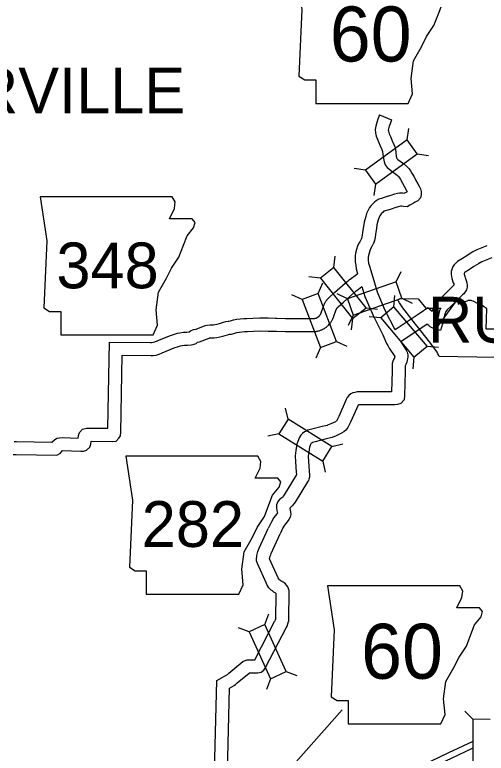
# Model space of a CAD drawing. Extents: x 535214 to 694517, y 381272 to 484355.
# Drawn here: x 547357 to 552787, y 463649 to 472159 of the extents above; entities that cross this region are included whole.
import ezdxf

# ---------------------------------------------------------------- set-up
doc = ezdxf.new("R2010")
doc.units = 0
for name, color, linetype in [('Level 10', 7, 'Continuous'), ('Level 11', 7, 'Continuous'), ('Level 19', 7, 'Continuous'), ('Level 20', 7, 'Continuous'), ('Level 21', 7, 'Continuous'), ('Level 6', 7, 'Continuous')]:
    doc.layers.add(name, color=color, linetype=linetype)

msp = doc.modelspace()

# ---------------------------------------------------------------- linework, layer by layer
at = {"layer": 'Level 10'}
msp.add_line((551558.8, 471004), (551697.7, 470947.3), dxfattribs=at)
for points in [[(551329.5, 469541.8), (551321.4, 469527.2), (551305.6, 469491), (551293.3, 469454.9), (551283, 469413.3), (551278.1, 469380.9), (551276.4, 469344.8), (551278.6, 469311.5), (551284.2, 469274.4), (551289.4, 469232.4), (551303.8, 469174.6)], [(551485.5, 469518), (551471.2, 469488.3), (551456.1, 469460.8), (551445.5, 469436.6), (551437.3, 469412.6), (551430.2, 469384), (551427.5, 469366.3), (551426.6, 469346.3), (551427.9, 469327.6), (551432.8, 469294.9), (551441.8, 469260.9), (551468.3, 469172.2)], [(550359, 468663.4), (550373.9, 468663), (550475.7, 468660.2), (550571.1, 468659.6), (550657.3, 468659), (550792.5, 468658.2), (550797.1, 468658.2), (550801, 468658.4), (550805.1, 468658.8), (550807.2, 468659.1), (550811.5, 468659.8), (550813.8, 468660.2), (550816.3, 468660.8), (550818.8, 468661.4), (550821.3, 468662.1), (550823.6, 468662.8), (550827.5, 468664.1), (550831.3, 468665.6), (550833.5, 468666.5), (550835.8, 468667.6), (550838.2, 468668.7), (550840.5, 468669.9), (550842.7, 468671.1), (550845, 468672.5), (550847.2, 468673.8), (550849.3, 468675.3), (550851.2, 468676.6), (550854.7, 468679.2), (550856.6, 468680.7), (550858.5, 468682.4), (550860.7, 468684.2), (550861.4, 468685), (550862.4, 468685.8), (550863.3, 468686.8), (550863.7, 468687.1), (550868, 468691.8), (550869.4, 468693.4), (550871.1, 468695.4), (550872.6, 468697.5), (550874, 468699.4), (550876.5, 468703), (550877.6, 468704.7), (550879.8, 468708.5), (550881, 468710.6), (550882, 468712.6), (550884, 468716.8), (550884.2, 468717.3), (550885.3, 468719.9), (550886.3, 468722.4), (550887.3, 468725.3), (550913.2, 468800.7), (550916.5, 468809.9), (550920.1, 468818.6), (550924.1, 468827.3), (550929.3, 468837.5), (550933.4, 468844.7), (550937.5, 468851.5), (550941.1, 468857), (550943.5, 468860.6), (550947.4, 468866), (550952.7, 468873.1), (550956.1, 468877.3), (550958, 468879.5), (550959.9, 468881.7), (550964.2, 468886.7), (550970.6, 468893.4), (550978.1, 468900.7), (551041.4, 468957.6), (551163.9, 469067.5), (551170.1, 469073), (551179.9, 469081.3), (551186.6, 469086.8), (551195.4, 469093.7), (551203.4, 469099.8), (551207.3, 469102.7), (551303.8, 469174.6)], [(551468.3, 469172.2), (551532, 468964.8), (551558.8, 468901.8), (551619.8, 468755.1), (551731.1, 468540.5), (551737.8, 468527.7)], [(550354.8, 468513.5), (550369.8, 468513), (550473.2, 468510.2), (550570.1, 468509.6), (550656.4, 468509), (550793, 468508.2), (550802.1, 468508.3), (550811.8, 468508.8), (550821.3, 468509.7), (550828.3, 468510.6), (550837.5, 468512), (550844.1, 468513.3), (550850.5, 468514.7), (550856.8, 468516.3), (550863.1, 468518), (550869.6, 468520), (550878.6, 468523.1), (550887.5, 468526.5), (550893.8, 468529.1), (550899.7, 468531.8), (550905.6, 468534.7), (550911.4, 468537.7), (550917.1, 468540.9), (550922.7, 468544.2), (550928.3, 468547.6), (550933.7, 468551.2), (550939.2, 468555.1), (550946.7, 468560.7), (550952, 468564.9), (550956.9, 468569.1), (550961.6, 468573.3), (550964.2, 468575.7), (550966.6, 468577.9), (550968.9, 468580.2), (550971.7, 468583.1), (550979.8, 468591.7), (550984.4, 468597), (550988.5, 468602.1), (550992.5, 468607.2), (550996.5, 468612.7), (551001.7, 468620.4), (551005.5, 468626.3), (551010.2, 468634.3), (551013.5, 468640.2), (551016.6, 468646.3), (551020.4, 468654.4), (551022.1, 468658.1), (551024.5, 468663.9), (551026.8, 468670), (551028.9, 468675.7), (551054.6, 468750.5), (551056.3, 468755.4), (551057.7, 468758.7), (551059.1, 468761.9), (551061.5, 468766.5), (551062.9, 468769), (551064.6, 468771.8), (551066.1, 468774.1), (551066.8, 468775.1), (551068.3, 468777.3), (551070.9, 468780.6), (551072.1, 468782.2), (551072.7, 468782.8), (551073.2, 468783.4), (551075, 468785.5), (551077.6, 468788.2), (551080.7, 468791.3), (551141.6, 468846), (551263.7, 468955.5), (551268.3, 468959.6), (551275.9, 468966.1), (551280.4, 468969.8), (551287, 468975), (551293, 468979.5), (551296.6, 468982.1), (551356.1, 469026.5)], [(551356.1, 469026.5), (551390.9, 468913.3), (551420.5, 468843.6), (551483.7, 468691.7), (551598, 468471.4), (551639.5, 468372.5)], [(552026.8, 468721.3), (551737.8, 468527.7)], [(552106, 468593.8), (551801.9, 468390.1)]]:
    msp.add_lwpolyline(points, dxfattribs=at)
at = {"layer": 'Level 11'}
for points in [[(551558.8, 471004), (551539, 470955.5), (551525.9, 470917.9), (551515.9, 470876.1), (551508.6, 470838.6), (551510.6, 470798.5), (551519.2, 470760.3), (551529.4, 470731.7), (551546.7, 470693.5), (551567, 470646.7), (551585.3, 470606.1), (551590, 470593.3), (551593.1, 470581.8), (551595.4, 470553.7), (551603, 470502.5), (551611, 470465.2), (551624.5, 470431), (551647.8, 470399.1), (551675, 470374.4), (551709.4, 470349.4), (551743.2, 470325.7), (551770.4, 470301.8), (551781.5, 470290.2), (551788.2, 470280.1), (551801.3, 470258.7), (551823.7, 470218.1), (551843, 470182.5), (551869.3, 470135.4), (551878.1, 470120.2), (551870.6, 470115.3), (551855.2, 470106.7), (551839.5, 470099.8), (551826.1, 470103.9), (551789, 470103.6), (551765.6, 470098.1), (551730.3, 470090), (551688.5, 470075.9), (551645.8, 470063), (551612, 470051.6), (551581.3, 470043.4), (551563, 470037.3), (551540.7, 470029.3), (551518.7, 470013.4), (551502.2, 470000.1), (551481, 469981.7), (551461.2, 469960.1), (551444.2, 469937.2), (551431.2, 469915.4), (551419.8, 469893.2), (551408, 469868.2), (551399, 469834), (551381.6, 469768.3), (551373.8, 469720.8), (551363.2, 469651.8), (551358.7, 469616.1), (551354.9, 469597.9), (551349.1, 469580.5), (551337.8, 469556.9), (551329.5, 469541.8)], [(551697.7, 470947.3), (551679.3, 470902.4), (551670, 470875.8), (551662.6, 470844.4), (551659.3, 470827.8), (551659.8, 470818.9), (551663.5, 470802.2), (551668.6, 470787.9), (551683.9, 470754.3), (551704.2, 470707.4), (551724.5, 470662.4), (551733.2, 470638.3), (551741.4, 470607.9), (551744.5, 470571), (551750.7, 470529.2), (551755.1, 470508.6), (551756.9, 470503.9), (551759.8, 470500), (551769.8, 470491), (551796.6, 470471.5), (551836.1, 470443.8), (551874.2, 470410.3), (551899.3, 470384.2), (551914.8, 470360.5), (551931, 470334.1), (551955.3, 470290.1), (551974.4, 470254.9), (551999.8, 470209.4), (552020, 470174.4), (552031.2, 470151.5), (552038.9, 470120.5), (552037.2, 470085.7), (552029.6, 470051.1), (552000, 470014.7), (551968.5, 470000.2), (551948.6, 469987), (551922.2, 469972.3), (551906.2, 469965.2), (551876.8, 469947.2), (551834.9, 469948.2), (551811, 469951.5), (551805.2, 469953.3), (551799.5, 469952), (551771.2, 469945.5), (551734.3, 469933), (551691.4, 469920.1), (551655.5, 469908), (551624.5, 469899.6), (551612, 469895.5), (551611.4, 469895.3), (551609.6, 469894), (551598.3, 469885), (551585.8, 469874.1), (551577, 469864.4), (551569.3, 469854), (551562.5, 469842.7), (551554.3, 469826.7), (551549.5, 469816.5), (551544, 469795.7), (551528.4, 469737), (551521.9, 469697.3), (551511.7, 469631.1), (551506.8, 469591.6), (551500, 469558.7), (551488.3, 469524), (551485.5, 469518)], [(552792.3, 469494.6), (552677.1, 469448.4), (552649.9, 469435.4), (552634.1, 469426.9), (552615, 469413.6), (552564.1, 469382.5), (552514.5, 469349.4), (552457.2, 469315.8), (552435.3, 469297.3), (552416.9, 469278.6), (552402.2, 469257.3), (552393.1, 469233.4), (552384.7, 469201.1), (552383.3, 469165.7), (552386.7, 469143.5), (552391.1, 469121.4), (552407.9, 469070.9), (552412.7, 469056.7), (552414.8, 469046.1), (552415.2, 469043.4), (552414.3, 469042.2), (552407.9, 469035.4), (552275.2, 468905.6), (552233.3, 468865.5), (552208.9, 468841.2), (552186.5, 468815.8)], [(552852, 469356.9), (552737.4, 469311), (552717.8, 469301.6), (552712.8, 469298.9), (552697.2, 469287.9), (552644.8, 469256.1), (552594.2, 469222.3), (552544.2, 469192.9), (552537.4, 469187.2), (552535.6, 469185.4), (552533.9, 469178.9), (552533.7, 469174.2), (552534.5, 469169.5), (552536.4, 469159.7), (552550.2, 469118.4), (552557.7, 469095.7), (552562.8, 469071.3), (552565.9, 469048), (552566.1, 469020.4), (552559, 468987.7), (552543.9, 468964.5), (552528.5, 468944.8), (552515.2, 468930.5), (552379.5, 468797.9), (552338.2, 468758.2), (552320.2, 468740.3)], [(552186.3, 468815.9), (552163.7, 468740.8), (552113.9, 468783.5), (552024.9, 468720)], [(552320.2, 468740.3), (552307.8, 468699), (552293.5, 468634.4), (552261.7, 468521.8), (552170.3, 468545.9), (552142.4, 468561.4), (552125.6, 468577.3), (552110.1, 468590.3), (552106.1, 468593.7)], [(547350.5, 467240.4), (547375.8, 467240.6), (547784.9, 467234.1), (547813.8, 467261.7), (547843.6, 467278.2), (547873.9, 467285), (547902.6, 467286.8), (548089.2, 467279.7), (548091.8, 467312.1), (548104.3, 467345), (548135.7, 467383.4), (548184.7, 467394.6), (548208.8, 467394.8), (548429.8, 467393.4), (548448.6, 468386.7), (548921, 468381.9), (548937.5, 468382.4), (548951.8, 468384.5), (548970.1, 468390.2), (548999.2, 468401.8), (549141.1, 468460.7), (549196.4, 468479.5), (549229.8, 468489.1), (549260.2, 468495.3), (549299.8, 468501), (549340.7, 468502.5), (549367.5, 468503.4), (549380.3, 468514.9), (549414.9, 468530.3), (549445.6, 468535.3), (549550.7, 468577.5), (549574.5, 468582.6), (549607.1, 468586.7), (549643.7, 468587.6), (549662.7, 468590.1), (549688.4, 468594.1), (549715, 468601.1), (549762.3, 468615.1), (549788.4, 468623.2), (549815.5, 468626.3), (549824.4, 468627), (549843.1, 468631.6), (549878.1, 468641.5), (549913.3, 468649.4), (549954.3, 468655.4), (549994.4, 468658.6), (550031.8, 468659.4), (550100.7, 468663), (550181.5, 468664.8), (550276, 468664.6), (550373.9, 468663)], [(547340.6, 467090.3), (547375.2, 467090.6), (547840.1, 467083.2), (547884.4, 467105.9), (547901.5, 467132), (547904.4, 467136.6), (548117.9, 467128.5), (548147.8, 467129.5), (548185.3, 467139.7), (548221.1, 467176.3), (548232, 467211.3), (548236.6, 467240.6), (548236.9, 467244.7), (548480.3, 467243.1), (548524.4, 467246.9), (548554.8, 467277.9), (548575.8, 467307.1), (548578.9, 467347.8), (548595.8, 468235.2), (548922.6, 468231.8), (548951.1, 468232.7), (548985.6, 468238), (549020, 468248.7), (549055.6, 468262.8), (549194.1, 468320.3), (549241.2, 468336.3), (549265.6, 468343.3), (549286, 468347.5), (549313.2, 468351.4), (549346.1, 468352.6), (549387.7, 468354.1), (549412.7, 468359.1), (549444.9, 468371.4), (549461, 468385.8), (549486.1, 468389.9), (549594.8, 468433.5), (549599.9, 468434.6), (549618.2, 468437), (549655.4, 468437.8), (549684.3, 468441.6), (549719.3, 468447.1), (549755.4, 468456.7), (549805.7, 468471.5), (549819.4, 468475.8), (549830.2, 468477), (549848.2, 468478.5), (549881.3, 468486.4), (549915, 468496.1), (549940.6, 468501.8), (549971.3, 468506.3), (550002, 468508.7), (550037.4, 468509.5), (550106.2, 468513.1), (550183, 468514.8), (550276, 468514.6), (550369.8, 468513)], [(551639.5, 468372.5), (551653.4, 468347.4), (551669.4, 468318.7), (551733.8, 468219.6), (551732.5, 468214.4), (551729.4, 468201.7), (551727.4, 468196.8), (551716, 468179), (551702.2, 468140)], [(551801.9, 468390.1), (551865.3, 468292.5), (551878, 468269.3), (551885.4, 468241.8), (551885.7, 468216), (551881.7, 468192.6), (551878.2, 468178.6), (551872.5, 468155.2), (551860.9, 468127), (551852.4, 468113.8)], [(551702.2, 468140), (551702.9, 468050.3)], [(551852.4, 468113.8), (551852.9, 468051.5)], [(551702.9, 468052.7), (551697.3, 467814.9), (551670.5, 467814.6), (551328.9, 467814.7), (551300.8, 467813.1), (551273.5, 467807.1), (551251.8, 467800.7), (551228.9, 467790.1), (551204.8, 467771.1), (551184.8, 467747.1), (551175, 467725.2), (551089.6, 467527.8), (551066, 467482.1), (551061.2, 467475.5), (551060.1, 467474.6), (551049.6, 467468.5), (550997.9, 467444.1), (550960.8, 467428.9), (550954.4, 467426.9), (550897.7, 467413.3), (550778, 467382.9), (550733.8, 467370.1), (550716.3, 467361.8), (550695.1, 467351.7), (550671.9, 467334.9), (550651.1, 467312.7), (550632.3, 467282.6), (550624.1, 467262.1), (550617, 467243.1), (550607.4, 467209.9), (550593.7, 467138.7), (550587.3, 467076.4), (550589.5, 467007.5), (550597.7, 466886.2), (550601.4, 466855.4), (550601.4, 466855.4), (550599.4, 466851.6), (550461.4, 466627.7), (550451, 466613.4), (550441.7, 466601.4), (550431.2, 466591.3), (550411.9, 466576.5), (550386.7, 466550.8), (550372.1, 466511.2), (550373.4, 466476.8), (550376.8, 466444.5), (550382.9, 466417.1), (550375.8, 466408), (550359.6, 466388.3), (550338.9, 466359.9), (550328.2, 466341.7), (550313.7, 466317.3), (550276.9, 466239.8)], [(551852.9, 468049.1), (551846.3, 467770.1), (551842.9, 467719.5), (551802.6, 467680.9), (551765, 467666.4), (551735.5, 467665.2), (551671.1, 467664.6), (551333.3, 467664.7), (551321.4, 467664), (551311, 467661.7), (551225.3, 467463.5), (551193.8, 467402.7), (551172, 467373), (551147.3, 467351.7), (551119.1, 467335.5), (551058.5, 467306.8), (551011.1, 467287.4), (550993.6, 467282.1), (550933.7, 467267.7), (550817.4, 467238.1), (550787, 467229.3), (550780.6, 467226.3), (550772, 467222.2), (550771.4, 467221.8), (550770.5, 467220.7), (550766.6, 467214.6), (550764, 467208), (550759.5, 467195.9), (550753.5, 467175), (550742.3, 467116.9), (550737.6, 467071.1), (550739.4, 467014.9), (550747.1, 466900.3), (550752.4, 466856.8), (550751.3, 466829.8), (550744.2, 466809), (550738.4, 466793), (550728.7, 466775.7), (550586, 466544), (550570.8, 466523.1), (550553.4, 466500.8), (550529.3, 466477.6), (550524.5, 466473.9), (550525, 466468.9), (550533.2, 466432.5), (550537.3, 466399.4), (550527.9, 466370.5), (550515, 466342.2), (550492.6, 466313.9), (550478.2, 466296.4), (550464.4, 466277.5), (550457.4, 466265.5), (550446.3, 466246.7), (550412.4, 466175.5)], [(550364.1, 465494), (550358, 465498), (550342.4, 465506.5), (550324.1, 465519.2), (550310.9, 465528.4), (550297.2, 465540.1), (550282.7, 465555.7), (550272.1, 465573.8), (550264.9, 465587.3), (550256.2, 465603.5), (550153.1, 465834.7), (550142.3, 465864.9), (550142.1, 465893.4), (550143.5, 465912.5), (550146, 465925.9), (550147.4, 465941.7), (550157.6, 465972.4), (550165.6, 465992.9), (550173.3, 466010.8), (550276.3, 466238.6)], [(550515.4, 465532.2), (550502.2, 465565.5), (550488.5, 465585.8), (550473.7, 465600.4), (550458.7, 465612.3), (550447.1, 465619.1), (550434.7, 465627), (550421.2, 465634.4), (550409.5, 465642.5), (550403.1, 465647), (550397.2, 465658), (550390.8, 465669.8), (550292.4, 465890.8), (550292.3, 465891), (550292.5, 465893.1), (550294.8, 465905.7), (550295.3, 465911), (550298.7, 465921.4), (550304.5, 465936.1), (550310.6, 465950.3), (550413, 466176.7)], [(550515.4, 465532.2), (550509.8, 465166.2)], [(550364.8, 465494), (550360.1, 465190.5)], [(549658.9, 463437.2), (549683.6, 464485.7), (549799.6, 464553.1), (549805.7, 464558), (549823.7, 464573.3), (549960.8, 464685.6), (549985.8, 464706.5), (550009.3, 464716.6), (550034.4, 464724.1), (550059.7, 464725.2), (550120.7, 464726.2), (550350, 465165.4), (550354.4, 465173.4), (550359.9, 465190.5)], [(549809, 463437.7), (549831.6, 464398.2), (549884.5, 464429), (549901.1, 464442.2), (549919.9, 464458.2), (550056.5, 464570), (550062.6, 464575.2), (550064, 464575.2), (550156, 464576.9), (550193.5, 464581.6), (550226.2, 464607.8), (550241, 464630.3), (550247.9, 464645.8), (550482.4, 465094.8), (550492.8, 465113.9), (550509.8, 465166.2)]]:
    msp.add_lwpolyline(points, dxfattribs=at)
at = {"layer": 'Level 19'}
for points in [[(550841.5, 462935.6), (551248.7, 463128.5), (551677.6, 463332.6), (552045.5, 463507.2), (552357.6, 463655.9), (552628.9, 463785.1)], [(550844.5, 462861), (551278.2, 463066.4), (551707.1, 463270.5), (552075, 463445.1), (552387.2, 463593.8), (552628.9, 463708.9)]]:
    msp.add_lwpolyline(points, dxfattribs=at)
at = {"layer": 'Level 20'}
for p, q in [((551875.5, 470717.7), (551895.6, 470848.1)), ((551992.6, 470558), (552123, 470537.9)), ((551396.4, 470366.5), (551266, 470386.6)), ((551513.5, 470206.8), (551493.4, 470076.4)), ((551031.7, 469246.4), (551046.3, 469377.6)), ((551751, 469080.4), (551808.4, 469199.3)), ((550877.1, 469122.7), (550745.9, 469137.3)), ((550852.2, 468948.4), (550906.4, 469068.8)), ((550667, 468878.3), (550546.6, 468932.6)), ((551190.1, 468885), (551071.2, 468942.4)), ((551723.8, 468794), (551735.5, 468925.5)), ((551816.2, 468893.5), (551935, 468836)), ((551402.7, 468782.5), (551533.9, 468767.8)), ((551255.2, 468698), (551197.8, 468579.1)), ((551248, 468658.8), (551233.4, 468527.6)), ((551572, 468666.9), (551440.5, 468678.6)), ((550877.3, 468322.8), (550823, 468202.5)), ((551062.5, 468392.9), (551182.8, 468338.6)), ((552105.1, 468338.5), (552236.5, 468326.8)), ((551953.2, 468211.4), (551941.6, 468079.9)), ((550505.4, 467498.3), (550475.7, 467627)), ((550400.3, 467330.5), (550271.7, 467300.9)), ((551008.9, 467183.3), (551137.5, 467212.9)), ((550903.9, 467015.4), (550933.5, 466886.8)), ((550237.3, 465130.6), (550283.9, 465254.1)), ((550056.9, 465048.9), (549933.4, 465095.5)), ((550482.3, 464589.5), (550605.8, 464542.9)), ((550301.9, 464507.8), (550255.4, 464384.3)), ((552634.3, 464040.1), (552541.4, 464134)), ((552634.3, 464040.1), (552631, 463462.2)), ((552832.3, 464039), (552634.3, 464040.1))]:
    msp.add_line(p, q, dxfattribs=at)
for points in [[(551513.5, 470206.8), (551992.6, 470558), (551875.5, 470717.7), (551396.4, 470366.5)], [(550877.1, 469122.7), (551248, 468658.8), (551402.7, 468782.5), (551031.7, 469246.4)], [(551751, 469080.4), (551190.1, 468885), (551255.2, 468698), (551816.2, 468893.5)], [(550667, 468878.3), (550877.3, 468322.8), (551062.5, 468392.9), (550852.2, 468948.4)], [(551572, 468666.9), (551953.2, 468211.4), (552105.1, 468338.5), (551723.8, 468794)], [(551008.9, 467183.3), (550505.4, 467498.3), (550400.3, 467330.5), (550903.9, 467015.4)], [(550482.3, 464589.5), (550237.3, 465130.6), (550056.9, 465048.9), (550301.9, 464507.8)]]:
    msp.add_lwpolyline(points, close=True, dxfattribs=at)
at = {"layer": 'Level 21'}
msp.add_line((551128.2, 464150.4), (550383.1, 463309.3), dxfattribs=at)
for points in [[(550586.2, 472727.8), (550662.3, 472220.3), (550628.5, 471450.5), (550696.2, 471408.2), (550823.1, 471408.2), (550823.1, 471137.6), (551888.9, 471137.6), (551939.6, 471247.5), (551922.7, 471425.2), (551948.1, 471628.2), (552041.1, 471788.9), (552100.4, 471907.3), (552184.9, 472034.2), (552235.7, 472169.5), (552278, 472279.5), (552354.1, 472372.6), (552371, 472431.8), (552337.2, 472474.1), (552075, 472474.1), (552134.2, 472592.5), (552142.6, 472668.6), (552107.6, 472727.1)], [(547649.2, 470060.6), (547725.3, 469553), (547691.5, 468783.3), (547759.2, 468741), (547886.1, 468741), (547886.1, 468470.3), (548951.9, 468470.3), (549002.6, 468580.3), (548985.7, 468757.9), (549011.1, 468960.9), (549104.1, 469121.6), (549163.4, 469240.1), (549247.9, 469367), (549298.7, 469502.3), (549341, 469612.3), (549417.1, 469705.3), (549434, 469764.5), (549400.2, 469806.8), (549138, 469806.8), (549197.2, 469925.2), (549205.6, 470001.4), (549170.6, 470059.8)], [(548635.5, 467071.1), (548711.7, 466563.5), (548677.8, 465793.8), (548745.5, 465751.5), (548872.4, 465751.5), (548872.4, 465480.8), (549938.2, 465480.8), (549989, 465590.7), (549972, 465768.4), (549997.4, 465971.4), (550090.5, 466132.1), (550149.7, 466250.5), (550234.3, 466377.4), (550285, 466512.8), (550327.3, 466622.7), (550403.5, 466715.8), (550420.4, 466775), (550386.5, 466817.3), (550124.3, 466817.3), (550183.5, 466935.7), (550192, 467011.8), (550156.9, 467070.3)], [(550960, 465577), (551036.1, 465069.5), (551002.3, 464299.7), (551069.9, 464257.4), (551196.8, 464257.4), (551196.8, 463986.7), (552262.7, 463986.7), (552313.4, 464096.7), (552296.5, 464274.3), (552321.9, 464477.3), (552414.9, 464638), (552474.1, 464756.5), (552558.7, 464883.4), (552609.5, 465018.7), (552651.8, 465128.7), (552727.9, 465221.7), (552744.8, 465280.9), (552711, 465323.2), (552448.8, 465323.2), (552508, 465441.6), (552516.4, 465517.8), (552481.3, 465576.2)]]:
    msp.add_lwpolyline(points, close=True, dxfattribs=at)
at = {"layer": 'Level 6'}
for points in [[(552118, 468409.3), (552006.8, 468551.7), (551972.2, 468595.3), (551828.1, 468782.4), (551788.4, 468840.8), (551768.3, 468873.4), (551797.2, 468889.5), (552004.2, 468885.5), (552091.5, 468777.4), (552265.8, 468776.7), (552261.5, 468771.2), (552257.7, 468765.7), (552254.4, 468759.3), (552250.6, 468749.9), (552248.6, 468742.9), (552246.4, 468734.7), (552232.2, 468674.3), (552226.8, 468655.3), (552222.6, 468646.6), (552218.5, 468639.5), (552212.7, 468633.5), (552206, 468610.7), (552238.1, 468578.8), (552454.7, 468876.8), (552463, 468876.7), (552462.1, 468824.4), (552481.8, 468833.4), (552504.8, 468841.7), (552532.2, 468851.5), (552566.8, 468862.9), (552583.4, 468868.3), (552594.2, 468870.6), (552603.8, 468871.2), (552610.5, 468869.3), (552619.3, 468866.8), (552631, 468862.6), (552646.7, 468855.1), (552676.7, 468840.1), (552730.8, 468814.5), (552745.2, 468807.3), (552761.5, 468797.5), (552771.9, 468790.2), (552777.3, 468785.6), (552780.9, 468781.4), (552788.4, 468770.8), (552783.5, 468540.5), (552924.5, 468537.8)], [(553111.4, 468204.1), (552246.4, 468220.7), (552237.7, 468239.3), (552231.2, 468251.8), (552220.5, 468270), (552201, 468298.2), (552178.8, 468329.2), (552163.9, 468349.1), (552148.6, 468369.6), (552118, 468409.3)]]:
    msp.add_lwpolyline(points, dxfattribs=at)

# ---------------------------------------------------------------- texts
at = {"layer": 'Level 21'}
for s, height, p in [('60', 633.6, (550985.2, 471620.5)), ('348', 528, (547836.9, 469006.4)), ('282', 528, (548819.5, 466025.9)), ('60', 633.6, (551345.9, 464507.2))]:
    msp.add_text(s, height=height, dxfattribs=at).set_placement(p)
at = {"layer": 'Level 6'}
for s, p in [('CEDARVILLE', (544925.5, 471023)), ('RUDY', (552116.1, 468380.9))]:
    msp.add_text(s, height=528, dxfattribs=at).set_placement(p)

doc.saveas('drawing.dxf')
